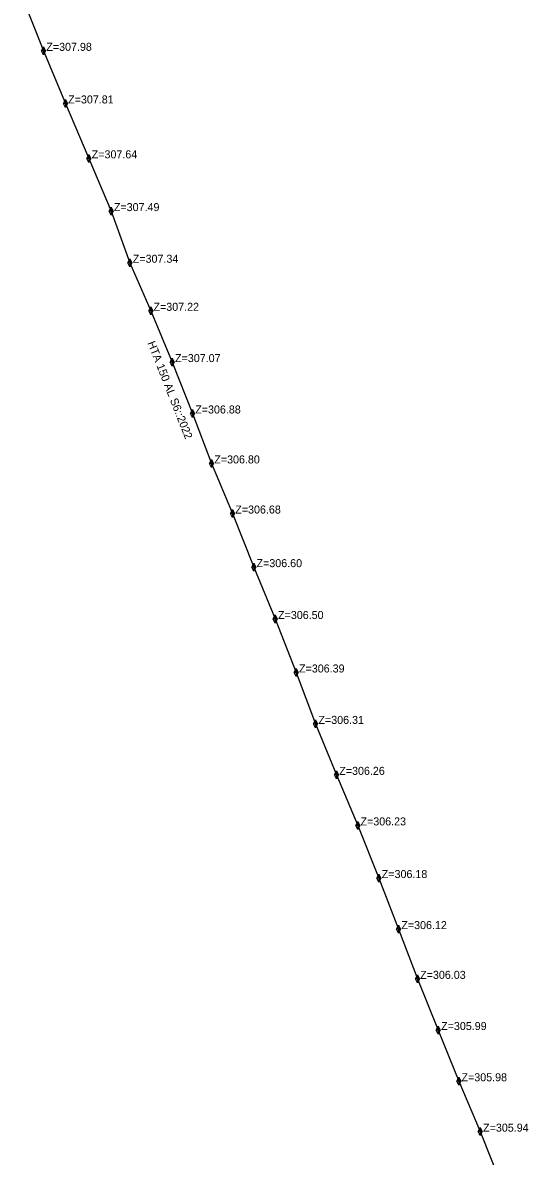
# Model space of a CAD drawing. Extents: x 799271 to 799523, y 67737 to 68184.
# Drawn here: x 799385.4 to 799410.6, y 67904.3 to 67960.9 of the extents above; entities that cross this region are included whole.
import ezdxf

# ---------------------------------------------------------------- set-up
doc = ezdxf.new("R2010")
doc.units = 0
doc.layers.add('PGOC_HTA_CONSTRUIT', color=7, linetype='Continuous')
doc.layers.add('PGOC_PTRL', color=7, linetype='Continuous')

msp = doc.modelspace()

# ---------------------------------------------------------------- linework, layer by layer
at = {"layer": 'PGOC_HTA_CONSTRUIT'}
msp.add_lwpolyline([(799385.38, 67962.141), (799386.421, 67959.533), (799387.512, 67956.904), (799388.69, 67954.162), (799389.798, 67951.526), (799390.742, 67948.946), (799391.776, 67946.545), (799392.853, 67943.983), (799393.862, 67941.415), (799394.814, 67938.92), (799395.863, 67936.417), (799396.925, 67933.738), (799398, 67931.148), (799399.048, 67928.476), (799400.018, 67925.907), (799401.058, 67923.362), (799402.119, 67920.836), (799403.182, 67918.205), (799404.159, 67915.656), (799405.1, 67913.17), (799406.148, 67910.613), (799407.166, 67908.053), (799408.246, 67905.536), (799409.304, 67902.864)], dxfattribs=at)
at = {"layer": 'PGOC_PTRL'}
for points in [[(799386.321, 67959.533), (799386.421, 67959.733), (799386.521, 67959.533), (799386.421, 67959.333), (799386.321, 67959.533)], [(799386.421, 67959.733), (799386.421, 67959.333)], [(799386.521, 67959.533), (799386.421, 67959.533), (799386.321, 67959.533)], [(799387.412, 67956.904), (799387.512, 67957.104), (799387.612, 67956.904), (799387.512, 67956.704), (799387.412, 67956.904)], [(799387.612, 67956.904), (799387.512, 67956.904), (799387.412, 67956.904)], [(799387.512, 67957.104), (799387.512, 67956.704)], [(799388.59, 67954.162), (799388.69, 67954.362), (799388.79, 67954.162), (799388.69, 67953.962), (799388.59, 67954.162)], [(799388.79, 67954.162), (799388.69, 67954.162), (799388.59, 67954.162)], [(799388.69, 67954.362), (799388.69, 67953.962)], [(799389.698, 67951.526), (799389.798, 67951.726), (799389.898, 67951.526), (799389.798, 67951.326), (799389.698, 67951.526)], [(799389.798, 67951.726), (799389.798, 67951.326)], [(799389.898, 67951.526), (799389.798, 67951.526), (799389.698, 67951.526)], [(799390.642, 67948.946), (799390.742, 67949.146), (799390.842, 67948.946), (799390.742, 67948.746), (799390.642, 67948.946)], [(799390.842, 67948.946), (799390.742, 67948.946), (799390.642, 67948.946)], [(799390.742, 67949.146), (799390.742, 67948.746)], [(799391.676, 67946.545), (799391.776, 67946.745), (799391.876, 67946.545), (799391.776, 67946.345), (799391.676, 67946.545)], [(799391.876, 67946.545), (799391.776, 67946.545), (799391.676, 67946.545)], [(799391.776, 67946.745), (799391.776, 67946.345)], [(799392.753, 67943.983), (799392.853, 67944.183), (799392.953, 67943.983), (799392.853, 67943.783), (799392.753, 67943.983)], [(799392.953, 67943.983), (799392.853, 67943.983), (799392.753, 67943.983)], [(799392.853, 67944.183), (799392.853, 67943.783)], [(799393.762, 67941.415), (799393.862, 67941.615), (799393.962, 67941.415), (799393.862, 67941.215), (799393.762, 67941.415)], [(799393.862, 67941.615), (799393.862, 67941.215)], [(799393.962, 67941.415), (799393.862, 67941.415), (799393.762, 67941.415)], [(799394.714, 67938.92), (799394.814, 67939.12), (799394.914, 67938.92), (799394.814, 67938.72), (799394.714, 67938.92)], [(799394.914, 67938.92), (799394.814, 67938.92), (799394.714, 67938.92)], [(799394.814, 67939.12), (799394.814, 67938.72)], [(799395.763, 67936.417), (799395.863, 67936.617), (799395.963, 67936.417), (799395.863, 67936.217), (799395.763, 67936.417)], [(799395.963, 67936.417), (799395.863, 67936.417), (799395.763, 67936.417)], [(799395.863, 67936.617), (799395.863, 67936.217)], [(799396.825, 67933.738), (799396.925, 67933.938), (799397.025, 67933.738), (799396.925, 67933.538), (799396.825, 67933.738)], [(799397.025, 67933.738), (799396.925, 67933.738), (799396.825, 67933.738)], [(799396.925, 67933.938), (799396.925, 67933.538)], [(799397.9, 67931.148), (799398, 67931.348), (799398.1, 67931.148), (799398, 67930.948), (799397.9, 67931.148)], [(799398, 67931.348), (799398, 67930.948)], [(799398.1, 67931.148), (799398, 67931.148), (799397.9, 67931.148)], [(799398.948, 67928.476), (799399.048, 67928.676), (799399.148, 67928.476), (799399.048, 67928.276), (799398.948, 67928.476)], [(799399.148, 67928.476), (799399.048, 67928.476), (799398.948, 67928.476)], [(799399.048, 67928.676), (799399.048, 67928.276)], [(799399.918, 67925.907), (799400.018, 67926.107), (799400.118, 67925.907), (799400.018, 67925.707), (799399.918, 67925.907)], [(799400.118, 67925.907), (799400.018, 67925.907), (799399.918, 67925.907)], [(799400.018, 67926.107), (799400.018, 67925.707)], [(799400.958, 67923.362), (799401.058, 67923.562), (799401.158, 67923.362), (799401.058, 67923.162), (799400.958, 67923.362)], [(799401.158, 67923.362), (799401.058, 67923.362), (799400.958, 67923.362)], [(799401.058, 67923.562), (799401.058, 67923.162)], [(799402.019, 67920.836), (799402.119, 67921.036), (799402.219, 67920.836), (799402.119, 67920.636), (799402.019, 67920.836)], [(799402.219, 67920.836), (799402.119, 67920.836), (799402.019, 67920.836)], [(799402.119, 67921.036), (799402.119, 67920.636)], [(799403.082, 67918.205), (799403.182, 67918.405), (799403.282, 67918.205), (799403.182, 67918.005), (799403.082, 67918.205)], [(799403.182, 67918.405), (799403.182, 67918.005)], [(799403.282, 67918.205), (799403.182, 67918.205), (799403.082, 67918.205)], [(799404.059, 67915.656), (799404.159, 67915.856), (799404.259, 67915.656), (799404.159, 67915.456), (799404.059, 67915.656)], [(799404.259, 67915.656), (799404.159, 67915.656), (799404.059, 67915.656)], [(799404.159, 67915.856), (799404.159, 67915.456)], [(799405, 67913.17), (799405.1, 67913.37), (799405.2, 67913.17), (799405.1, 67912.97), (799405, 67913.17)], [(799405.2, 67913.17), (799405.1, 67913.17), (799405, 67913.17)], [(799405.1, 67913.37), (799405.1, 67912.97)], [(799406.048, 67910.613), (799406.148, 67910.813), (799406.248, 67910.613), (799406.148, 67910.413), (799406.048, 67910.613)], [(799406.248, 67910.613), (799406.148, 67910.613), (799406.048, 67910.613)], [(799406.148, 67910.813), (799406.148, 67910.413)], [(799407.066, 67908.053), (799407.166, 67908.253), (799407.266, 67908.053), (799407.166, 67907.853), (799407.066, 67908.053)], [(799407.266, 67908.053), (799407.166, 67908.053), (799407.066, 67908.053)], [(799407.166, 67908.253), (799407.166, 67907.853)], [(799408.146, 67905.536), (799408.246, 67905.736), (799408.346, 67905.536), (799408.246, 67905.336), (799408.146, 67905.536)], [(799408.346, 67905.536), (799408.246, 67905.536), (799408.146, 67905.536)], [(799408.246, 67905.736), (799408.246, 67905.336)]]:
    msp.add_lwpolyline(points, dxfattribs=at)

# ---------------------------------------------------------------- texts
at = {"layer": 'PGOC_HTA_CONSTRUIT'}
msp.add_text('HTA 150 AL S6::2022', height=0.4, rotation=291.4648, dxfattribs=at).set_placement((799391.609, 67944.94))
at = {"layer": 'PGOC_PTRL'}
for s, p in [('Z=307.98', (799386.561, 67959.533)), ('Z=307.81', (799387.652, 67956.904)), ('Z=307.64', (799388.83, 67954.162)), ('Z=307.49', (799389.938, 67951.526)), ('Z=307.34', (799390.882, 67948.946)), ('Z=307.22', (799391.916, 67946.545)), ('Z=307.07', (799392.993, 67943.983)), ('Z=306.88', (799394.002, 67941.415)), ('Z=306.80', (799394.954, 67938.92)), ('Z=306.68', (799396.003, 67936.417)), ('Z=306.60', (799397.065, 67933.738)), ('Z=306.50', (799398.14, 67931.148)), ('Z=306.39', (799399.188, 67928.476)), ('Z=306.31', (799400.158, 67925.907)), ('Z=306.26', (799401.198, 67923.362)), ('Z=306.23', (799402.259, 67920.836)), ('Z=306.18', (799403.322, 67918.205)), ('Z=306.12', (799404.299, 67915.656)), ('Z=306.03', (799405.24, 67913.17)), ('Z=305.99', (799406.288, 67910.613)), ('Z=305.98', (799407.306, 67908.053)), ('Z=305.94', (799408.386, 67905.536))]:
    msp.add_text(s, height=0.4, dxfattribs=at).set_placement(p)

doc.saveas('drawing.dxf')
